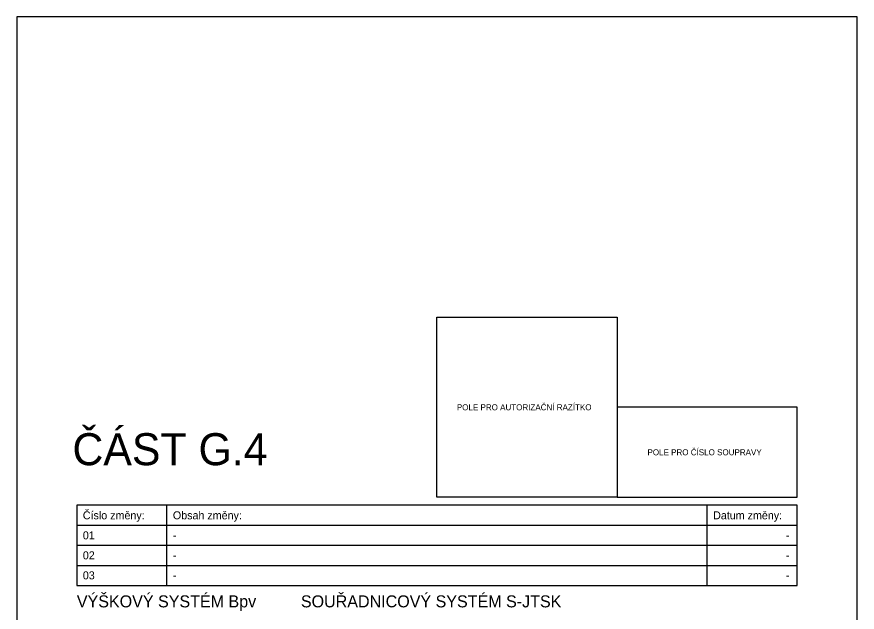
# Model space of a CAD drawing. Extents: x 1619 to 1829, y 760 to 1057.
# Drawn here: x 1618.7 to 1828.7, y 908.2 to 1056.9 of the extents above; entities that cross this region are included whole.
import ezdxf

# ---------------------------------------------------------------- set-up
doc = ezdxf.new("R2010")
doc.units = 0
for name, color, linetype in [('101_PRIKOP', 7, 'Continuous'), ('104_SVODIDLO', 7, 'Continuous'), ('104_ZPEVNENI', 7, 'Continuous'), ('106_KRAJNICE', 7, 'Continuous'), ('120_ZPEVNENI', 7, 'Continuous')]:
    doc.layers.add(name, color=color, linetype=linetype)

msp = doc.modelspace()

# ---------------------------------------------------------------- linework, layer by layer
at = {"layer": '104_SVODIDLO'}
for points in [[(1768.65, 936.87), (1723.65, 936.87), (1723.65, 981.87), (1768.65, 981.87)], [(1768.65, 936.87), (1813.65, 936.87), (1813.65, 959.37), (1768.65, 959.37)]]:
    msp.add_lwpolyline(points, close=True, dxfattribs=at)
at = {"layer": '106_KRAJNICE'}
for p, q in [((1656.15, 914.87), (1656.15, 934.87)), ((1791.15, 914.87), (1791.15, 934.87)), ((1633.65, 929.87), (1813.65, 929.87)), ((1633.65, 924.87), (1813.65, 924.87)), ((1633.65, 919.87), (1813.65, 919.87))]:
    msp.add_line(p, q, dxfattribs=at)
msp.add_lwpolyline([(1633.65, 914.87), (1813.65, 914.87), (1813.65, 934.87), (1633.65, 934.87)], close=True, dxfattribs=at)
at = {"layer": '120_ZPEVNENI'}
msp.add_lwpolyline([(1618.65, 759.93), (1828.65, 759.93), (1828.65, 1056.93), (1618.65, 1056.93)], close=True, dxfattribs=at)

# ---------------------------------------------------------------- texts
at = {"layer": '101_PRIKOP'}
for s, p in [('01', (1635.15, 926.37)), ('-', (1657.65, 926.37)), ('-', (1810.81, 926.37)), ('02', (1635.15, 921.37)), ('-', (1657.65, 921.37)), ('-', (1810.81, 921.37)), ('03', (1635.15, 916.37)), ('-', (1657.65, 916.37)), ('-', (1810.81, 916.37))]:
    msp.add_text(s, height=2, rotation=360, dxfattribs=at).set_placement(p)
at = {"layer": '104_SVODIDLO'}
for s, p in [('POLE PRO AUTORIZAČNÍ RAZÍTKO', (1728.61, 958.62)), ('POLE PRO ČÍSLO SOUPRAVY', (1776.25, 947.37))]:
    msp.add_text(s, height=1.5, rotation=360, dxfattribs=at).set_placement(p)
at = {"layer": '104_ZPEVNENI'}
for s, p in [('Číslo změny:', (1635.15, 931.37)), ('Obsah změny:', (1657.65, 931.37)), ('Datum změny:', (1792.65, 931.37))]:
    msp.add_text(s, height=2, rotation=360, dxfattribs=at).set_placement(p)
at = {"layer": '120_ZPEVNENI'}
msp.add_text('ČÁST G.4', height=8, rotation=360, dxfattribs=at).set_placement((1632.55, 944.89))
for s, p in [('VÝŠKOVÝ SYSTÉM Bpv', (1633.65, 909.37)), ('SOUŘADNICOVÝ SYSTÉM S-JTSK', (1689.64, 909.37))]:
    msp.add_text(s, height=3, dxfattribs=at).set_placement(p)

doc.saveas('drawing.dxf')
